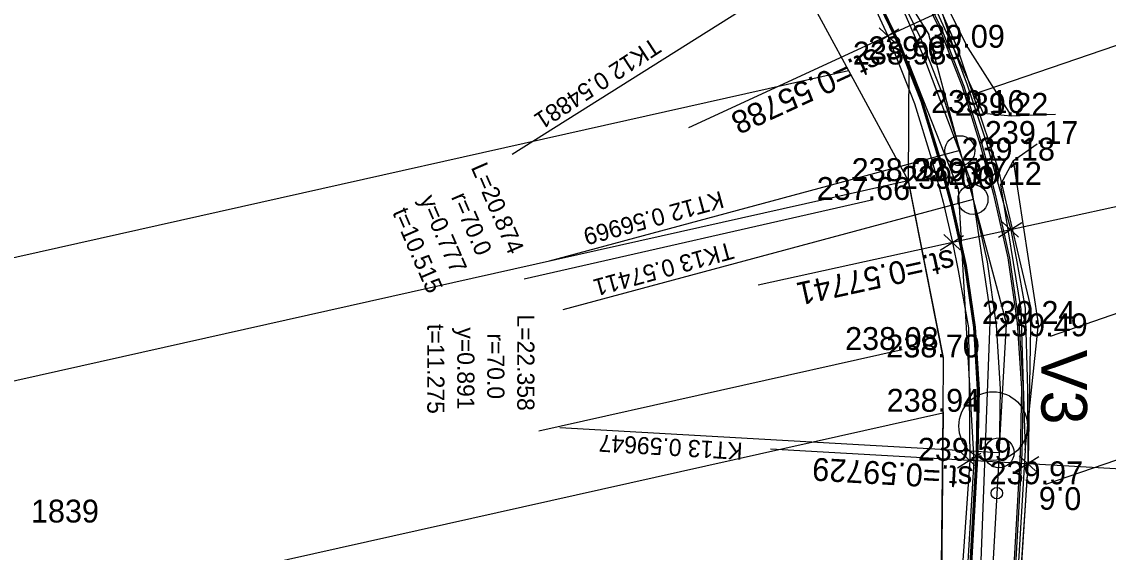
# Model space of a CAD drawing. Extents: x -601754 to -601440, y -1201912 to -1200862.
# Drawn here: x -601597.9 to -601502.8, y -1201422.6 to -1201376.3 of the extents above; entities that cross this region are included whole.
import ezdxf

# ---------------------------------------------------------------- set-up
doc = ezdxf.new("R2010")
doc.units = 0
for name, color, linetype in [('Hranice parcel', 7, 'Continuous'), ('Parcelní čísla', 7, 'Continuous'), ('u_drén', 7, 'Continuous'), ('u_hrany', 7, 'Continuous'), ('u_krizky', 7, 'Continuous'), ('u_návrh', 7, 'Continuous'), ('u_oblouky', 7, 'Continuous'), ('u_osa', 7, 'Continuous'), ('u_popis oblouky', 7, 'Continuous'), ('u_pricne_cesta', 7, 'Continuous'), ('u_staniceni', 7, 'Continuous'), ('u_terénní úpravy', 7, 'Continuous'), ('u_vrty IGP', 7, 'Continuous'), ('u_vyska', 7, 'Continuous')]:
    doc.layers.add(name, color=color, linetype=linetype)

msp = doc.modelspace()

# ---------------------------------------------------------------- linework, layer by layer
at = {"layer": 'Hranice parcel'}
for p, q in [((-601666.27, -1201412.04), (-601525.57, -1201380.51)), ((-601525.57, -1201380.51), (-601520.35, -1201390.13)), ((-601659.87, -1201421.39), (-601520.35, -1201390.13)), ((-601647.48, -1201439.51), (-601517.31, -1201410.46))]:
    msp.add_line(p, q, dxfattribs=at)
for points in [[(-601514.66, -1201382.62), (-601516.09, -1201378.41), (-601518.22, -1201373.55), (-601531.84, -1201350.34)], [(-601532.14, -1201368.61), (-601531.08, -1201370.35), (-601525.57, -1201380.51)], [(-601474.94, -1201369.02), (-601479.57, -1201370.6), (-601514.66, -1201382.62)], [(-601511.82, -1201455.51), (-601511.63, -1201442.04), (-601509.82, -1201414.6), (-601509.57, -1201401.34), (-601512.41, -1201389.28), (-601514.66, -1201382.62)], [(-601520.35, -1201390.13), (-601517.26, -1201405.61), (-601517.31, -1201410.46)], [(-601517.31, -1201410.46), (-601517.81, -1201455.91), (-601517.67, -1201457.2)]]:
    msp.add_lwpolyline(points, dxfattribs=at)
at = {"layer": 'u_drén'}
msp.add_lwpolyline([(-601553.194, -1201317.864), (-601552.875, -1201318.687), (-601546.074, -1201333.752), (-601538.46, -1201348.424), (-601530.069, -1201362.635), (-601525.78, -1201369.465), (-601523.226, -1201373.891), (-601521.024, -1201378.462), (-601519.169, -1201383.184), (-601517.66, -1201388.066), (-601516.532, -1201392.263), (-601515.324, -1201397.601), (-601514.551, -1201402.98), (-601514.21, -1201408.403), (-601514.303, -1201413.875), (-601516.032, -1201444.23), (-601516.195, -1201450.215), (-601516.005, -1201456.227), (-601515.463, -1201462.19), (-601510.248, -1201505.371), (-601509.825, -1201509.657), (-601509.591, -1201513.936), (-601509.544, -1201518.242), (-601509.788, -1201540.615)], dxfattribs=at)
at = {"layer": 'u_hrany'}
for points in [[(-601528.04, -1201358.49), (-601518.86, -1201373.11), (-601513.78, -1201384.24)], [(-601525.27, -1201359.89), (-601518.2, -1201372.38), (-601515.12, -1201378.53), (-601511.32, -1201384.48)], [(-601510.66, -1201493.25), (-601511.13, -1201487.34), (-601514.2, -1201454.81), (-601514.64, -1201441.92), (-601513.13, -1201401.75), (-601514.86, -1201390.2), (-601518.87, -1201379.54), (-601520.9, -1201374.92)], [(-601517.26, -1201405.61), (-601520.32, -1201390.19), (-601520.24, -1201380), (-601515.97, -1201390.87)], [(-601513.78, -1201384.24), (-601511.32, -1201384.48)], [(-601511.32, -1201384.48), (-601507.43, -1201384.34)], [(-601512.26, -1201390.52), (-601511.11, -1201388.4), (-601509.06, -1201386.94)], [(-601510.09, -1201413.72), (-601508.92, -1201402.68), (-601511.11, -1201388.4)], [(-601515.97, -1201390.87), (-601514.58, -1201414.64), (-601515.47, -1201429.34), (-601515.96, -1201454.63), (-601512.47, -1201487.32), (-601513.15, -1201505.52)], [(-601512.26, -1201390.52), (-601510.47, -1201401.41), (-601510.09, -1201413.72), (-601511.79, -1201441.97), (-601511.82, -1201455.52), (-601508.66, -1201487.01), (-601505.94, -1201512.07), (-601505.14, -1201523.95), (-601505.37, -1201547.09), (-601506.1, -1201561.67), (-601507, -1201580.71), (-601507.44, -1201612.51), (-601506.59, -1201624.18), (-601504.84, -1201632.93)], [(-601523.39, -1201391.84), (-601553.96, -1201398.76)], [(-601507.87, -1201403.76), (-601495.07, -1201399.33)], [(-601520.87, -1201404.96), (-601552.65, -1201412.05)], [(-601517.26, -1201410.36), (-601517.73, -1201457.2)], [(-601508.3, -1201416.7), (-601495.96, -1201412.46)]]:
    msp.add_lwpolyline(points, dxfattribs=at)
at = {"layer": 'u_krizky'}
for p, q in [((-601521.158, -1201376.899), (-601523.211, -1201378.178)), ((-601521.451, -1201378.125), (-601522.878, -1201376.805)), ((-601510.393, -1201393.855), (-601512.446, -1201395.135)), ((-601510.687, -1201395.082), (-601512.113, -1201393.762)), ((-601515.485, -1201394.969), (-601517.538, -1201396.249)), ((-601515.779, -1201396.195), (-601517.205, -1201394.876)), ((-601513.966, -1201414.025), (-601516.018, -1201415.305)), ((-601514.259, -1201415.251), (-601515.685, -1201413.932)), ((-601508.897, -1201414.314), (-601510.95, -1201415.593)), ((-601509.19, -1201415.54), (-601510.617, -1201414.22))]:
    msp.add_line(p, q, dxfattribs=at)
at = {"layer": 'u_návrh'}
for points in [[(-601563.542, -1201278.368), (-601555.153, -1201301.929), (-601549.253, -1201317.17), (-601542.541, -1201332.04), (-601535.025, -1201346.521), (-601526.716, -1201360.593), (-601522.417, -1201367.44), (-601519.753, -1201372.056), (-601517.425, -1201376.89), (-601515.462, -1201381.885), (-601513.889, -1201386.977), (-601512.721, -1201391.321), (-601511.461, -1201396.888), (-601510.644, -1201402.577), (-601510.283, -1201408.313), (-601510.38, -1201414.02), (-601512.11, -1201444.395)], [(-601567.28, -1201279.795), (-601558.903, -1201303.323), (-601552.944, -1201318.716), (-601546.141, -1201333.785), (-601538.525, -1201348.46), (-601530.133, -1201362.674), (-601525.844, -1201369.504), (-601523.292, -1201373.926), (-601521.093, -1201378.492), (-601519.24, -1201383.209), (-601517.732, -1201388.087), (-601516.605, -1201392.281), (-601515.398, -1201397.615), (-601514.626, -1201402.988), (-601514.285, -1201408.405), (-601514.378, -1201413.873), (-601516.107, -1201444.227)], [(-601549.753, -1201316.295), (-601549.392, -1201317.228), (-601542.676, -1201332.105), (-601535.157, -1201346.594), (-601526.844, -1201360.671), (-601522.546, -1201367.518), (-601519.886, -1201372.126), (-601517.562, -1201376.951), (-601515.604, -1201381.935), (-601514.033, -1201387.018), (-601512.867, -1201391.357), (-601511.609, -1201396.915), (-601510.793, -1201402.592), (-601510.433, -1201408.317), (-601510.53, -1201414.015), (-601512.26, -1201444.389), (-601512.419, -1201450.207), (-601512.236, -1201455.996), (-601511.709, -1201461.793), (-601506.495, -1201504.959), (-601506.06, -1201509.368), (-601505.817, -1201513.812), (-601505.769, -1201518.242), (-601506.187, -1201556.503)], [(-601553.136, -1201317.803), (-601552.806, -1201318.658), (-601546.006, -1201333.72), (-601538.394, -1201348.388), (-601530.005, -1201362.596), (-601525.716, -1201369.427), (-601523.16, -1201373.856), (-601520.956, -1201378.432), (-601519.098, -1201383.159), (-601517.588, -1201388.045), (-601516.46, -1201392.245), (-601515.25, -1201397.587), (-601514.477, -1201402.972), (-601514.135, -1201408.402), (-601514.228, -1201413.878), (-601515.957, -1201444.233), (-601516.12, -1201450.215), (-601515.93, -1201456.223), (-601515.388, -1201462.182), (-601510.174, -1201505.363), (-601509.75, -1201509.651), (-601509.516, -1201513.934), (-601509.469, -1201518.242), (-601509.714, -1201540.624)]]:
    msp.add_lwpolyline(points, dxfattribs=at)
at = {"layer": 'u_oblouky'}
for p, q in [((-601524.131, -1201368.472), (-601554.997, -1201387.854)), ((-601524.131, -1201368.472), (-601518.539, -1201377.377)), ((-601515.811, -1201387.532), (-601518.539, -1201377.377)), ((-601515.811, -1201387.532), (-601551.769, -1201397.194)), ((-601514.663, -1201391.801), (-601550.567, -1201401.449)), ((-601514.663, -1201391.801), (-601511.737, -1201402.69)), ((-601512.379, -1201413.946), (-601511.737, -1201402.69)), ((-601512.379, -1201413.946), (-601550.819, -1201411.757))]:
    msp.add_line(p, q, dxfattribs=at)
for centre in [(-601515.811, -1201387.532), (-601514.663, -1201391.801), (-601512.379, -1201413.946)]:
    msp.add_circle(centre, 1.311, dxfattribs=at)
at = {"layer": 'u_osa'}
msp.add_lwpolyline([(-601557.028, -1201302.626), (-601551.099, -1201317.943), (-601544.341, -1201332.912), (-601536.775, -1201347.491), (-601528.425, -1201361.634), (-601524.131, -1201368.472), (-601521.523, -1201372.991), (-601519.259, -1201377.691), (-601517.351, -1201382.547), (-601515.811, -1201387.532), (-601514.663, -1201391.801), (-601513.43, -1201397.251), (-601512.635, -1201402.782), (-601512.284, -1201408.359), (-601512.379, -1201413.946), (-601514.108, -1201444.311)], dxfattribs=at)
at = {"layer": 'u_pricne_cesta'}
for points in [[(-601503.238, -1201368.813), (-601521.408, -1201377.171), (-601539.577, -1201385.53)], [(-601494.396, -1201390.748), (-601513.934, -1201395.021), (-601533.473, -1201399.294)], [(-601492.458, -1201415.908), (-601512.426, -1201414.771), (-601532.393, -1201413.633)]]:
    msp.add_lwpolyline(points, dxfattribs=at)
at = {"layer": 'u_staniceni'}
msp.add_circle((-601512.58, -1201417.476), 0.5, dxfattribs=at)
at = {"layer": 'u_terénní úpravy'}
for points in [[(-601563.549, -1201276.755), (-601560.467, -1201285.585), (-601555.466, -1201299.915), (-601555, -1201301.25), (-601553.702, -1201304.613), (-601549.711, -1201315.986), (-601546.008, -1201323.122), (-601539.52, -1201337.25), (-601537.344, -1201340.958), (-601533.54, -1201348.31), (-601527.44, -1201357.911), (-601522.351, -1201366.758), (-601519.36, -1201371.808), (-601517.434, -1201375.343), (-601516.299, -1201378.722), (-601515.181, -1201381.785), (-601513.502, -1201386.766), (-601512.274, -1201391.071), (-601511.36, -1201394.458), (-601510.891, -1201396.937), (-601510.105, -1201401.304), (-601509.884, -1201408.41), (-601509.865, -1201414.917), (-601511.161, -1201434.926)], [(-601565.037, -1201287.212), (-601558.145, -1201306.245), (-601553.368, -1201318.894), (-601550.549, -1201325.146), (-601546.519, -1201333.968), (-601541.758, -1201343.289), (-601538.578, -1201348.49), (-601532.041, -1201360.744), (-601526.088, -1201369.629), (-601523.664, -1201374.122), (-601522.125, -1201377.501), (-601519.788, -1201383.401), (-601518.29, -1201388.248), (-601517.27, -1201392.04), (-601516.455, -1201395.572), (-601515.96, -1201398.024), (-601515.065, -1201403.029), (-601514.933, -1201414.628), (-601514.933, -1201414.628), (-601516.331, -1201434.631)]]:
    msp.add_lwpolyline(points, dxfattribs=at)
at = {"layer": 'u_vrty IGP'}
msp.add_circle((-601512.903, -1201411.617), 3, dxfattribs=at)

# ---------------------------------------------------------------- texts
at = {"layer": 'Parcelní čísla'}
msp.add_text('1839', height=2, dxfattribs=at).set_placement((-601597.112, -1201420.046))
at = {"layer": 'u_oblouky'}
for s, rotation, p in [('L=20.874', 293.45631, (-601558.634, -1201388.986)), ('r=70.0', 293.45631, (-601560.369, -1201391.581)), ('y=0.777', 293.45631, (-601563.139, -1201391.792)), ('t=10.515', 293.45631, (-601565.51, -1201392.923)), ('t=11.275', 270, (-601562.426, -1201402.681)), ('L=22.358', 270, (-601554.551, -1201401.854)), ('y=0.891', 270, (-601559.801, -1201402.976)), ('r=70.0', 270, (-601557.176, -1201403.507))]:
    msp.add_text(s, height=1.5, rotation=rotation, dxfattribs=at).set_placement(p)
at = {"layer": 'u_popis oblouky'}
for s, rotation, p in [('TK12 0.54881', 213.2152, (-601542.661, -1201377.574)), ('KT12 0.56969', 195.41062, (-601536.732, -1201391.03)), ('TK13 0.57411', 195.40097, (-601535.865, -1201395.491)), ('KT13 0.59647', 176.68413, (-601534.786, -1201413.076))]:
    msp.add_text(s, height=1.5, rotation=rotation, dxfattribs=at).set_placement(p)
at = {"layer": 'u_pricne_cesta'}
for s, rotation, p in [('st.=0.55788', 204.7047, (-601523.254, -1201378.481)), ('st.=0.57741', 192.33694, (-601516.501, -1201396.123)), ('st.=0.59729', 176.74013, (-601514.628, -1201415.174))]:
    msp.add_text(s, height=2, rotation=rotation, dxfattribs=at).set_placement(p)
at = {"layer": 'u_staniceni'}
msp.add_text('0.6', height=2, rotation=179.35018, dxfattribs=at).set_placement((-601505.174, -1201416.962))
at = {"layer": 'u_vrty IGP'}
msp.add_text('V3', height=4, rotation=270, dxfattribs=at).set_placement((-601508.683, -1201404.936))
at = {"layer": 'u_vyska'}
for s, p in [('239.09', (-601520.058, -1201378.53)), ('238.98', (-601525.172, -1201380)), ('239.05', (-601523.832, -1201379.54)), ('239.16', (-601518.335, -1201384.24)), ('239.22', (-601516.252, -1201384.48)), ('239.17', (-601513.625, -1201386.94)), ('239.18', (-601515.671, -1201388.4)), ('238.09', (-601525.282, -1201390.19)), ('239.07', (-601519.827, -1201390.2)), ('239.00', (-601520.964, -1201390.87)), ('239.12', (-601516.821, -1201390.52)), ('237.66', (-601528.341, -1201391.84)), ('239.24', (-601513.88, -1201402.68)), ('239.49', (-601512.805, -1201403.76)), ('238.08', (-601525.857, -1201404.96)), ('238.70', (-601522.252, -1201405.61)), ('238.94', (-601522.22, -1201410.36)), ('239.59', (-601519.487, -1201414.64)), ('239.97', (-601513.212, -1201416.7))]:
    msp.add_text(s, height=2, dxfattribs=at).set_placement(p)

doc.saveas('drawing.dxf')
